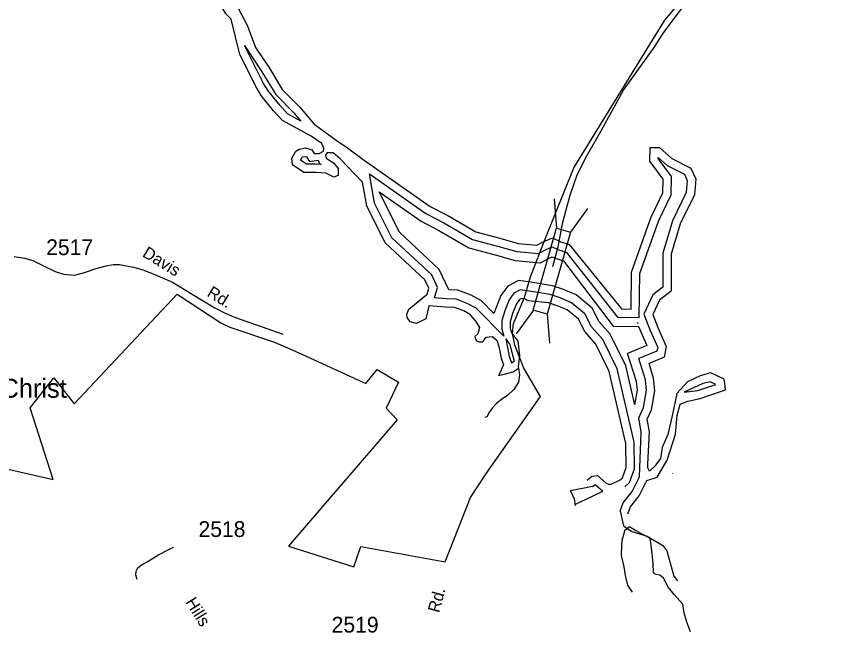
# Model space of a CAD drawing. Extents: x 1364363 to 1407445, y 538563 to 573342.
# Drawn here: x 1379352 to 1385775, y 538601 to 543485 of the extents above; entities that cross this region are included whole.
import ezdxf

# ---------------------------------------------------------------- set-up
doc = ezdxf.new("R2010")
doc.units = 0
for name, color, linetype in [('Exist Boundary Political City Limit New', 7, 'Continuous'), ('Exist Cultural Church Label', 7, 'Continuous'), ('Exist Hydrographic Buffer Line', 7, 'Continuous'), ('Exist Hydrographic Creek Double Shore', 7, 'Continuous'), ('Exist Hydrographic Creek Single Shore', 7, 'Continuous'), ('Exist Hydrographic Island Shore', 7, 'Continuous'), ('Exist Road Secondary Structure Standard Bridge CELL', 7, 'Continuous'), ('Exist Road Secondary Type 51 Attributed', 7, 'Continuous'), ('Exist Road Secondary Type 51 Label', 7, 'Continuous'), ('Exist Road Secondary Type 51 Number Label', 7, 'Continuous')]:
    doc.layers.add(name, color=color, linetype=linetype)

msp = doc.modelspace()

# ---------------------------------------------------------------- linework, layer by layer
at = {"layer": 'Exist Boundary Political City Limit New'}
msp.add_lwpolyline([(1377998.1, 540192.7), (1379644.1, 539813.9), (1379462, 540383.1), (1379649.6, 540620.7), (1379811.2, 540414.1), (1380626.8, 541283.8), (1380973.1, 541056.2), (1381044.5, 541022.8), (1381398.1, 540903.4), (1381586.5, 540821.6), (1382123.6, 540576.3), (1382212.1, 540686.4), (1382382, 540586.9), (1382283.8, 540378.8), (1382371.9, 540286.9), (1381570.1, 539359.1), (1381510.6, 539286.4), (1382027.5, 539123.6), (1382084, 539283.4), (1382752.6, 539161.6), (1382953.1, 539672.3), (1383079.4, 539866.1), (1383507.6, 540472.9), (1383375.8, 540697.8), (1383303.9, 540879.9), (1383283.9, 540972.9), (1383291.9, 541050.5), (1383379.8, 541257.9), (1383427.6, 541420.6), (1383547.5, 541726.9), (1383771.2, 542285.1), (1384493.2, 543453), (1384815.2, 543836.1)], dxfattribs=at)
at = {"layer": 'Exist Hydrographic Buffer Line'}
for points in [[(1381607.6, 542654.9), (1381502.8, 542711.9), (1381441.4, 542779.3), (1381348.3, 542894.9), (1381312.6, 542953.4), (1381161.1, 543252.8)], [(1381161.1, 543252.8), (1381297.7, 543045.4), (1381408.3, 542864.1), (1381552.4, 542719.9), (1381607.6, 542654.9)], [(1381746, 542345.3), (1381753.2, 542320.1), (1381768.3, 542310.3), (1381728.7, 542313.6), (1381652.2, 542313.6), (1381604, 542345.7), (1381617.2, 542368.2), (1381620.1, 542370), (1381641.4, 542374.3), (1381652.7, 542370.6), (1381676.2, 542332.9), (1381746, 542345.3)], [(1383713, 541614.3), (1384117.1, 541102), (1384288.2, 541098.6), (1384294.2, 541445.8), (1384440.5, 541862.5), (1384541.1, 542070.5), (1384543.9, 542215.3), (1384438.9, 542358.5), (1384439, 542366.1), (1384510.5, 542302.3), (1384646.9, 542233.5), (1384669.9, 542184), (1384661.6, 542089.1), (1384551.4, 541864.4), (1384475.1, 541608.3), (1384477, 541339.3), (1384397.4, 541279), (1384325.2, 541125.8), (1384376.1, 540994.4), (1384435.1, 540861.4), (1384429.4, 540832.4), (1384285.9, 540772.6)], [(1382151, 542235.2), (1382597.6, 541922.6), (1382740.6, 541847.7), (1382967.8, 541716.8), (1383166.1, 541664.5), (1383318.4, 541620.6), (1383491.3, 541604.9), (1383555.9, 541639.3), (1383600.2, 541657.5), (1383644.3, 541637.7), (1383713, 541614.3)], [(1382667.8, 541253.1), (1382690.8, 541337.2), (1382645.2, 541435.5), (1382330, 541730.7), (1382192.5, 542002.9), (1382151, 542235.2)], [(1382227.6, 542093.5), (1382560, 541860.8), (1382705.8, 541784.4), (1382940.1, 541649.4), (1383146.9, 541595), (1383305.1, 541549.4), (1383506.3, 541531), (1383586.6, 541573.9), (1383598.9, 541578.9), (1383617.8, 541570.4), (1383689.7, 541546)], [(1382779.4, 541317.6), (1382704.8, 541478.6), (1382388.7, 541774.7), (1382227.6, 542093.5)], [(1383689.7, 541546), (1384081.6, 541030.5), (1384282.8, 541026.5)], [(1383411.3, 541381.3), (1383333.5, 541391.7), (1383247.7, 541347.2), (1383193.5, 541272.6), (1383138.2, 541131.1)], [(1384253.7, 540407.3), (1384182.5, 540716.5), (1384060, 540965.3), (1383972.1, 541064.4), (1383916.6, 541173.1), (1383789.1, 541277), (1383689.2, 541320.5), (1383600.6, 541350), (1383413.5, 541381)], [(1383138.2, 541131.1), (1383039.9, 541229.3), (1382956.4, 541276.3), (1382852.6, 541314.1), (1382779.4, 541317.6)], [(1383401.7, 541309.8), (1383346.5, 541317.2), (1383296.1, 541291), (1383257.4, 541237.7), (1383223.6, 541151.5), (1383201, 541075.1), (1383199.5, 541006.1), (1383215.5, 540951.7)], [(1384174.7, 539756.6), (1384211.5, 539790.4), (1384251.2, 539898.2), (1384248.3, 540109.4), (1384114.1, 540692.2), (1383999.6, 540924.6), (1383912, 541023.4), (1383859.2, 541126.7), (1383751.2, 541214.8), (1383663.4, 541253), (1383583.2, 541279.8), (1383401.7, 541309.8)], [(1383215.5, 540951.7), (1382995.9, 541171.3), (1382926.2, 541210.5), (1382838.2, 541242.5), (1382758.9, 541246.3), (1382667.8, 541253.1)], [(1384272.7, 541061.6), (1384277, 541050.5)], [(1384282.8, 541026.5), (1384349.2, 540877.1), (1384197.3, 540813.8)], [(1383230.8, 540928.4), (1383259.7, 540793.2), (1383277.8, 540738.8), (1383297.4, 540751.3)], [(1383230.8, 540928.4), (1383263.6, 540884.5), (1383297.4, 540751.3)], [(1384253.7, 540407.3), (1384274.3, 540522.9), (1384267.5, 540590.2), (1384197.3, 540813.8)], [(1384290.7, 539836.8), (1384303.9, 540189.2), (1384285.1, 540302.3), (1384323.4, 540386.6), (1384347.1, 540520.1), (1384338.6, 540604.7), (1384285.9, 540772.6)], [(1384646.2, 540505.7), (1384753.2, 540518.9), (1384895, 540568.6), (1384851, 540589.9), (1384793.2, 540574.3), (1384646.2, 540505.7)], [(1384137.8, 539565.1), (1384161.4, 539630), (1384233.8, 539719.7), (1384290.7, 539836.8)], [(1383919.3, 539758.6), (1383743.5, 539724.8), (1383773.2, 539660.7), (1383781.7, 539609.9), (1383785, 539618.5), (1383919.3, 539683.7), (1384001.9, 539721.8)], [(1383919.3, 539758.6), (1383939.3, 539775.8), (1384001.9, 539721.8)], [(1384137.8, 539565.1), (1384165.1, 539447.1), (1384230.7, 539403.4), (1384351.6, 539365.7), (1384475.1, 539290.8), (1384508, 539250.5), (1384562.1, 539049.1), (1384592.2, 539012.2)]]:
    msp.add_lwpolyline(points, dxfattribs=at)
at = {"layer": 'Exist Hydrographic Creek Double Shore'}
for points in [[(1380755.6, 544414.1), (1380755.6, 544392.8), (1380765.6, 544356), (1380732.2, 544289), (1380742.2, 544238.8), (1380739.2, 544136.2), (1380755.9, 543982.2), (1380796, 543838.3), (1380879.6, 543781.4), (1380966.6, 543681), (1380976.6, 543610.8), (1380986.6, 543543.8), (1381010.2, 543507.7), (1381055, 543462.8)], [(1381004.6, 543804.9), (1381089, 543682.9), (1381089, 543592.6), (1381115.7, 543539), (1381182.6, 543415.2), (1381249.5, 543237.9), (1381353.2, 543080.6), (1381460.3, 542904.9), (1381600.7, 542764.4), (1381714.4, 542630.5), (1381888.3, 542503.3), (1381978.6, 542443.1), (1382102.3, 542349.4), (1382631.8, 541978.8), (1382772.2, 541905.2), (1382993, 541778), (1383183.6, 541727.8), (1383330.6, 541685.4), (1383477.8, 541672), (1383527.9, 541698.8), (1383601.5, 541728.9), (1383668.4, 541698.8), (1383734.1, 541676.4)], [(1382988.4, 541074), (1382952.2, 541120.6), (1382898.7, 541150.7), (1382825.1, 541177.4), (1382754.9, 541180.8), (1382621.1, 541190.8), (1382611.1, 541144), (1382597.7, 541087.1), (1382524.2, 541050.3), (1382474, 541063.7), (1382450.6, 541097.1), (1382447.3, 541123.9), (1382464, 541164.1), (1382607.8, 541282.5), (1382621.1, 541331.4), (1382591, 541396.3), (1382276.7, 541690.8), (1382129.6, 541981.9), (1382096.1, 542169.3), (1381919.9, 542355.1), (1381863, 542401.9), (1381816.2, 542401.9), (1381802.8, 542385.2), (1381809.5, 542361.7), (1381866.4, 542324.9), (1381903.3, 542278.2), (1381903.2, 542224.5), (1381869.7, 542211.2), (1381806.2, 542241.3), (1381725.9, 542248), (1381632.3, 542248), (1381542, 542308.2), (1381535.3, 542358.4), (1381568.8, 542415.3), (1381595.5, 542432), (1381645.7, 542442.1), (1381695.8, 542425.3), (1381712.5, 542398.6), (1381752.7, 542398.6), (1381786.1, 542415.3), (1381789.5, 542438.7), (1381772.7, 542475.5), (1381689.1, 542535.8), (1381461.7, 542659.6), (1381391.5, 542736.6), (1381294.5, 542857), (1381255.2, 542921.4), (1381123.5, 543181.7), (1381055, 543462.8)], [(1383734.1, 541676.4), (1384148.8, 541167), (1384223.8, 541165.5), (1384228.8, 541457.5), (1384379.8, 541887.8), (1384475.8, 542086.1), (1384477.8, 542194.4), (1384372.8, 542337.6), (1384374.8, 542445.9), (1384449.8, 542444.4), (1384547.8, 542357), (1384696.8, 542281.9), (1384736.8, 542195.7), (1384725.8, 542071.2), (1384612.8, 541840.4), (1384540.8, 541599), (1384542.8, 541306.8), (1384449.8, 541236.5), (1384396.6, 541123.3), (1384436.7, 541019.5), (1384503.6, 540868.9), (1384486.9, 540785.3), (1384366.5, 540735.1)], [(1383734.1, 541676.4), (1384148.8, 541167), (1384223.8, 541165.5), (1384228.8, 541457.5), (1384379.8, 541887.8), (1384475.8, 542086.1), (1384477.8, 542194.4), (1384372.8, 542337.6), (1384374.8, 542445.9), (1384449.8, 542444.4), (1384547.8, 542357), (1384696.8, 542281.9), (1384736.8, 542195.7), (1384725.8, 542071.2), (1384612.8, 541840.4), (1384540.8, 541599), (1384542.8, 541306.8), (1384449.8, 541236.5), (1384396.6, 541123.3), (1384436.7, 541019.5), (1384503.6, 540868.9), (1384486.9, 540785.3), (1384366.5, 540735.1)], [(1383409.1, 541229.8), (1383380.2, 541246.5), (1383358.4, 541249.4), (1383340.1, 541239.9), (1383315.4, 541205.9), (1383285.8, 541130.2), (1383266.4, 541064.9), (1383265.4, 541014.9), (1383276.6, 540976.7), (1383326.7, 540909.7), (1383340.1, 540796), (1383331, 540707.5), (1383332.6, 540695.9)], [(1383409.1, 541229.8), (1383380.2, 541246.5), (1383358.4, 541249.4), (1383340.1, 541239.9), (1383315.4, 541205.9), (1383285.8, 541130.2), (1383266.4, 541064.9), (1383265.4, 541014.9), (1383276.6, 540976.7), (1383326.7, 540909.7), (1383340.1, 540796), (1383331, 540707.5), (1383332.6, 540695.9)], [(1383876.5, 539808.4), (1383913.8, 539840.5), (1383958.9, 539845.4), (1384027.6, 539786.3), (1384046.8, 539777.2), (1384067.4, 539779), (1384137.8, 539811.8), (1384155.4, 539828), (1384185.4, 539909.5), (1384182.8, 540101.4), (1384051.8, 540670), (1383944.6, 540887.7), (1383857.3, 540986.2), (1383807.1, 541084.6), (1383716.8, 541158.2), (1383639.9, 541191.7), (1383569.6, 541215.1), (1383409.1, 541229.8)], [(1383876.5, 539808.4), (1383913.8, 539840.5), (1383958.9, 539845.4), (1384027.6, 539786.3), (1384046.8, 539777.2), (1384067.4, 539779), (1384137.8, 539811.8), (1384155.4, 539828), (1384185.4, 539909.5), (1384182.8, 540101.4), (1384051.8, 540670), (1383944.6, 540887.7), (1383857.3, 540986.2), (1383807.1, 541084.6), (1383716.8, 541158.2), (1383639.9, 541191.7), (1383569.6, 541215.1), (1383409.1, 541229.8)], [(1382988.4, 541074), (1383022.4, 541020.2), (1383009.1, 540970), (1382985.6, 540946.5), (1382995.7, 540916.4), (1383019.1, 540906.4), (1383049.2, 540906.4), (1383075.9, 540943.2), (1383122.7, 540946.5), (1383159.5, 540919.8), (1383176.3, 540869.6), (1383196.3, 540775.9), (1383213, 540725.7), (1383189.6, 540668.8), (1383172.9, 540638.7), (1383229.8, 540652.1), (1383289.9, 540668.8), (1383332.6, 540695.9)], [(1382988.4, 541074), (1383022.4, 541020.2), (1383009.1, 540970), (1382985.6, 540946.5), (1382995.7, 540916.4), (1383019.1, 540906.4), (1383049.2, 540906.4), (1383075.9, 540943.2), (1383122.7, 540946.5), (1383159.5, 540919.8), (1383176.3, 540869.6), (1383196.3, 540775.9), (1383213, 540725.7), (1383189.6, 540668.8), (1383172.9, 540638.7), (1383229.8, 540652.1), (1383289.9, 540668.8), (1383332.6, 540695.9)], [(1384356.5, 539937.6), (1384369.8, 540192.9), (1384353.1, 540293.3), (1384386.5, 540367), (1384413.3, 540517.6), (1384403.3, 540617.9), (1384366.5, 540735.1)], [(1384356.5, 539937.6), (1384369.8, 540192.9), (1384353.1, 540293.3), (1384386.5, 540367), (1384413.3, 540517.6), (1384403.3, 540617.9), (1384366.5, 540735.1)], [(1384349.8, 539808.1), (1384430, 539833.5), (1384510.3, 539967.4), (1384577.1, 540174.9), (1384590.5, 540322.1), (1384613.9, 540412.5), (1384674.1, 540435.9), (1384770.6, 540455.5), (1384971.3, 540525.8), (1384967.9, 540579.3), (1384961.2, 540609.4), (1384857.6, 540659.6), (1384770.6, 540636.2), (1384670.3, 540589.3), (1384586.7, 540495.6), (1384570, 540418.7), (1384546.6, 540308.2), (1384516.5, 540171), (1384469.7, 540067.3), (1384456.3, 539980.3), (1384412.8, 539920), (1384369.3, 539879.9), (1384356, 539906.7), (1384356.5, 539937.6)], [(1384349.8, 539808.1), (1384430, 539833.5), (1384510.3, 539967.4), (1384577.1, 540174.9), (1384590.5, 540322.1), (1384613.9, 540412.5), (1384674.1, 540435.9), (1384770.6, 540455.5), (1384971.3, 540525.8), (1384967.9, 540579.3), (1384961.2, 540609.4), (1384857.6, 540659.6), (1384770.6, 540636.2), (1384670.3, 540589.3), (1384586.7, 540495.6), (1384570, 540418.7), (1384546.6, 540308.2), (1384516.5, 540171), (1384469.7, 540067.3), (1384456.3, 539980.3), (1384412.8, 539920), (1384369.3, 539879.9), (1384356, 539906.7), (1384356.5, 539937.6)], [(1384555, 539865.9), (1384552.8, 539861.7)], [(1384199.4, 539542.6), (1384219.3, 539597.3), (1384289.6, 539684.3), (1384349.8, 539808.1)], [(1384199.4, 539542.6), (1384219.3, 539597.3), (1384289.6, 539684.3), (1384349.8, 539808.1)]]:
    msp.add_lwpolyline(points, dxfattribs=at)
at = {"layer": 'Exist Hydrographic Creek Single Shore'}
msp.add_lwpolyline([(1383332.6, 540695.9), (1383339.7, 540644.9), (1383332.5, 540585.2), (1383295.3, 540527.7), (1383246.2, 540479.5), (1383199.6, 540450), (1383154.8, 540414.8), (1383126.1, 540381.8), (1383101.5, 540350.2), (1383080.6, 540310.4), (1383064.5, 540305)], dxfattribs=at)
at = {"layer": 'Exist Hydrographic Island Shore'}
for points in [[(1384235.4, 538921.6), (1384199.1, 538978), (1384179, 539054.9), (1384169, 539121.9), (1384148.9, 539212.2), (1384152.3, 539295.9), (1384152.5, 539334.9), (1384172.5, 539398.5), (1384174.5, 539414)], [(1384174.5, 539414), (1384212.4, 539443.1), (1384262.6, 539409.7), (1384373, 539349.4), (1384383, 539272.5), (1384396.4, 539152), (1384400.4, 539075.6)], [(1384694, 538608.5), (1384667.2, 538685.5), (1384643.8, 538759.1), (1384633.8, 538826), (1384566.9, 538903), (1384520.1, 538959.9), (1384480, 539033.5), (1384453.2, 539056.9), (1384423.1, 539063.6), (1384400.4, 539075.6)]]:
    msp.add_lwpolyline(points, dxfattribs=at)
at = {"layer": 'Exist Road Secondary Structure Standard Bridge CELL'}
for p, q in [((1383614.7, 542037.7), (1383632.3, 541806.4)), ((1383880, 541962.5), (1383743.7, 541774.8)), ((1383450.3, 541156.9), (1383313.9, 540969.3)), ((1383559.2, 541126.1), (1383576.8, 540894.7))]:
    msp.add_line(p, q, dxfattribs=at)
msp.add_lwpolyline([(1383743.7, 541774.8), (1383559.7, 541125.9), (1383448.3, 541157.5), (1383632.3, 541806.4)], close=True, dxfattribs=at)
at = {"layer": 'Exist Road Secondary Type 51 Attributed'}
for points in [[(1383603.9, 541501.8), (1383647.2, 541657.5), (1383683.6, 541852.3), (1383741.8, 542066.8), (1383797.7, 542229.3), (1383873.7, 542378.3), (1383990.8, 542582.2), (1384165.4, 542900.5), (1384408.6, 543238.6), (1384476.4, 543346.8), (1384556.8, 543457.1), (1384678, 543614.7), (1384719, 543661.9), (1384901.2, 543856.1), (1385107.5, 544040.9), (1385299.1, 544190), (1385585.8, 544430.1), (1385734.9, 544532), (1385852.1, 544598)], [(1379335.1, 541582.2), (1379418.9, 541567.2), (1379484.1, 541549.1), (1379567.9, 541507), (1379661, 541461.8), (1379726.2, 541440.8), (1379813, 541434.7), (1379892.2, 541454.3), (1379994.6, 541490.4), (1380066, 541508.5), (1380121.8, 541517.5), (1380171.5, 541517.5), (1380224.2, 541508.5), (1380283.2, 541496.4), (1380354.6, 541475.4), (1380438.4, 541445.3), (1380590.2, 541377.6), (1380806.1, 541245.1), (1380927.1, 541175.9), (1381007.8, 541133.8), (1381090, 541099.1), (1381170.7, 541069), (1381301.1, 541023.9), (1381465.5, 540966.7)], [(1380599, 539276.2), (1380574.8, 539266.6), (1380548.4, 539253.1), (1380483.1, 539219.3), (1380398.7, 539165.5), (1380348.6, 539138.6), (1380311.9, 539108), (1380300.9, 539086), (1380298.5, 539061.6), (1380307, 539024.9)]]:
    msp.add_lwpolyline(points, dxfattribs=at)

# ---------------------------------------------------------------- texts
at = {"layer": 'Exist Cultural Church Label'}
msp.add_text('Jesus Christ', height=150, dxfattribs=at).set_placement((1378648.8, 540462.6))
at = {"layer": 'Exist Road Secondary Type 51 Label'}
for s, rotation, p in [('Davis        Rd.', 328.46311, (1380345.1, 541585.8)), ('Hills', 301.74934, (1380689.3, 538844)), ('Rd.', 74.86412, (1382703.7, 538753.9))]:
    msp.add_text(s, height=95, rotation=rotation, dxfattribs=at).set_placement(p)
at = {"layer": 'Exist Road Secondary Type 51 Number Label'}
for s, p in [('2517', (1379589.7, 541592.4)), ('2518', (1380796.9, 539359.6)), ('2519', (1381851.9, 538602.3))]:
    msp.add_text(s, height=125, dxfattribs=at).set_placement(p)

doc.saveas('drawing.dxf')
